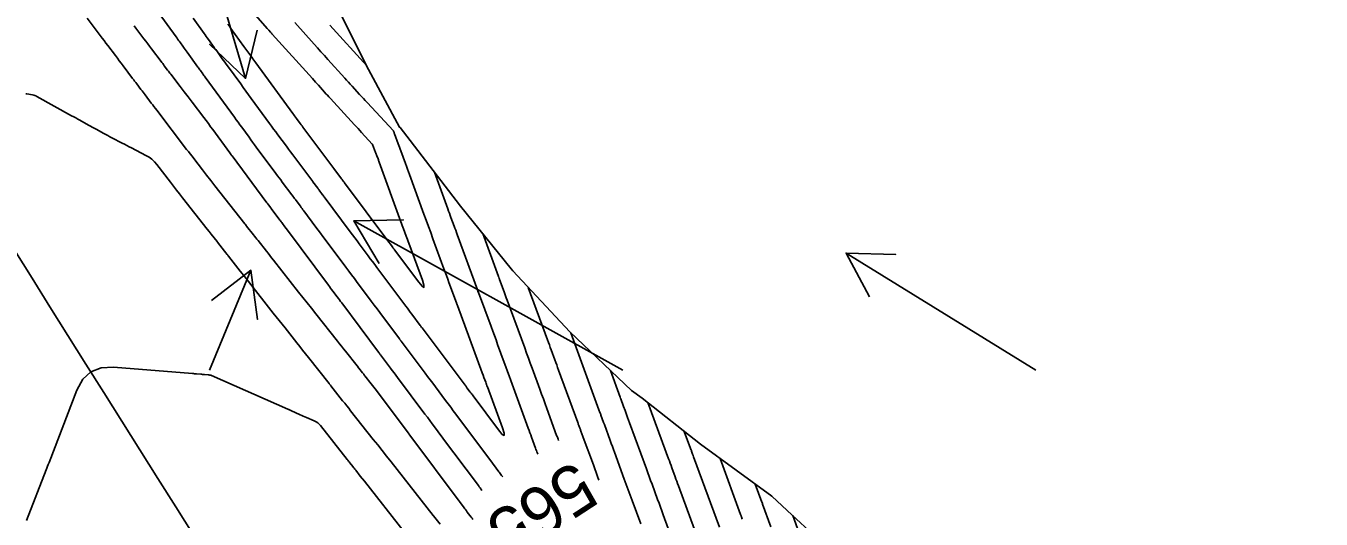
# Model space of a CAD drawing. Extents: x 954385 to 988206, y 1868364 to 1924553.
# Drawn here: x 957284.9 to 957441.7, y 1920650.9 to 1920710.5 of the extents above; entities that cross this region are included whole.
import ezdxf

# ---------------------------------------------------------------- set-up
doc = ezdxf.new("R2010")
doc.units = 0
for name, color, linetype in [('24', 7, 'Continuous'), ('26', 7, 'Continuous'), ('5', 7, 'Continuous'), ('6', 7, 'Continuous'), ('7', 7, 'Continuous'), ('Default', 7, 'Continuous')]:
    doc.layers.add(name, color=color, linetype=linetype)

msp = doc.modelspace()

# ---------------------------------------------------------------- linework, layer by layer
at = {"layer": '24'}
msp.add_lwpolyline([(957321.88, 1920714.2), (957326.37, 1920705.27), (957330.11, 1920698.3), (957330.2, 1920698.26), (957331.42, 1920696.68), (957337.51, 1920688.75), (957343.63, 1920681.18), (957343.82, 1920680.95), (957350.73, 1920673.54), (957358.19, 1920666.47), (957359.5, 1920665.55), (957366.53, 1920659.98), (957375.17, 1920653.68), (957377.65, 1920651.39), (957382.74, 1920646.71)], dxfattribs=at)
at = {"layer": '26'}
for points in [[(957307.13, 1920718.93), (957311.5, 1920704.2), (957307.14, 1920708.33), (957311.5, 1920704.2), (957312.9, 1920710.03)], [(957357.13, 1920668.93), (957324.58, 1920686.97), (957330.58, 1920687.08), (957324.58, 1920686.97), (957327.67, 1920681.83)], [(957407.13, 1920668.93), (957384.17, 1920683.08), (957390.17, 1920682.91), (957384.17, 1920683.08), (957387.02, 1920677.8)], [(957307.13, 1920668.93), (957312.14, 1920681.01), (957312.92, 1920675.06), (957312.14, 1920681.01), (957307.38, 1920677.36)]]:
    msp.add_lwpolyline(points, dxfattribs=at)
at = {"layer": '6'}
for points in [[(957300.93, 1920712.2), (957303.09, 1920709.21), (957303.2, 1920709.06), (957303.31, 1920708.9), (957303.42, 1920708.75), (957303.53, 1920708.6), (957303.97, 1920707.99), (957304.08, 1920707.84), (957304.19, 1920707.69), (957304.3, 1920707.53), (957304.41, 1920707.38), (957305.73, 1920705.56), (957305.8, 1920705.46), (957305.87, 1920705.36), (957305.94, 1920705.25), (957306.02, 1920705.15), (957306.31, 1920704.75), (957306.38, 1920704.65), (957306.45, 1920704.55), (957306.53, 1920704.45), (957306.6, 1920704.35), (957310.14, 1920699.5), (957310.36, 1920699.19), (957310.58, 1920698.89), (957310.8, 1920698.59), (957311.02, 1920698.29), (957311.91, 1920697.08), (957312.13, 1920696.78), (957312.35, 1920696.48), (957312.57, 1920696.18), (957312.79, 1920695.88), (957315.17, 1920692.69), (957315.36, 1920692.43), (957315.56, 1920692.18), (957315.75, 1920691.92), (957315.94, 1920691.66), (957317.08, 1920690.14), (957317.09, 1920690.12), (957317.12, 1920690.08), (957317.13, 1920690.07), (957317.42, 1920689.68), (957317.47, 1920689.62), (957317.52, 1920689.55), (957317.57, 1920689.48), (957317.62, 1920689.42), (957318.13, 1920688.73), (957318.23, 1920688.6), (957318.33, 1920688.46), (957318.43, 1920688.32), (957318.54, 1920688.19), (957320, 1920686.22), (957320.28, 1920685.85), (957320.56, 1920685.48), (957320.84, 1920685.1), (957321.11, 1920684.73), (957323.63, 1920681.36), (957323.98, 1920680.9), (957324.32, 1920680.44), (957324.66, 1920679.99), (957325, 1920679.53), (957326.37, 1920677.7), (957326.71, 1920677.25), (957327.05, 1920676.79), (957327.4, 1920676.33), (957327.74, 1920675.88), (957330.11, 1920672.7), (957330.14, 1920672.67), (957330.16, 1920672.64), (957330.21, 1920672.58), (957330.23, 1920672.55), (957330.25, 1920672.52), (957330.32, 1920672.44), (957330.34, 1920672.41), (957333.22, 1920668.57), (957333.53, 1920668.16), (957333.84, 1920667.75), (957334.15, 1920667.33), (957334.46, 1920666.92), (957335.7, 1920665.26), (957336.01, 1920664.85), (957336.32, 1920664.44), (957336.63, 1920664.02), (957336.94, 1920663.61), (957340.4, 1920658.98), (957341.04, 1920658.13), (957342.14, 1920656.65), (957342.22, 1920656.54), (957342.31, 1920656.43), (957342.39, 1920656.32), (957342.48, 1920656.2), (957342.61, 1920656.03)], [(957326.15, 1920705.7), (957321.7, 1920710.64)], [(957346.85, 1920658.78), (957346.81, 1920658.9), (957346.75, 1920659.05), (957346.69, 1920659.2), (957346.64, 1920659.35), (957346.58, 1920659.51), (957346.1, 1920660.82), (957346, 1920661.09), (957345.91, 1920661.36), (957345.81, 1920661.63), (957345.71, 1920661.9), (957343.59, 1920667.69), (957343.39, 1920668.23), (957343.19, 1920668.78), (957342.99, 1920669.32), (957342.79, 1920669.86), (957341.99, 1920672.02), (957341.8, 1920672.57), (957341.6, 1920673.11), (957341.4, 1920673.65), (957341.2, 1920674.19), (957339.69, 1920678.3), (957339.66, 1920678.35), (957339.62, 1920678.47), (957339.6, 1920678.52), (957339.57, 1920678.6), (957339.56, 1920678.65), (957337.11, 1920685.31), (957337.02, 1920685.57), (957336.92, 1920685.83), (957336.83, 1920686.09), (957336.73, 1920686.35), (957336.35, 1920687.38), (957336.26, 1920687.64), (957336.16, 1920687.9), (957336.07, 1920688.15), (957335.97, 1920688.41), (957334.36, 1920692.85)], [(957366.27, 1920648.44), (957363.88, 1920654.94), (957363.78, 1920655.22), (957363.68, 1920655.49), (957363.58, 1920655.76), (957363.48, 1920656.03), (957363.08, 1920657.12), (957362.98, 1920657.39), (957362.88, 1920657.67), (957362.78, 1920657.94), (957362.68, 1920658.21), (957360.18, 1920665.02)]]:
    msp.add_lwpolyline(points, dxfattribs=at)
at = {"layer": '7'}
for points in [[(957309.36, 1920710.74), (957309.54, 1920710.5), (957309.63, 1920710.37), (957309.72, 1920710.25), (957311.3, 1920708.06), (957311.42, 1920707.9), (957311.54, 1920707.73), (957311.66, 1920707.57), (957311.78, 1920707.4), (957312.26, 1920706.75), (957312.38, 1920706.58), (957312.5, 1920706.42), (957312.62, 1920706.25), (957312.74, 1920706.09), (957317.21, 1920699.97), (957317.32, 1920699.81), (957317.43, 1920699.66), (957317.54, 1920699.51), (957317.65, 1920699.36), (957318.11, 1920698.76), (957318.22, 1920698.6), (957318.33, 1920698.45), (957318.44, 1920698.3), (957318.56, 1920698.15), (957322.16, 1920693.32), (957322.18, 1920693.3), (957323.12, 1920692.05), (957323.18, 1920691.97), (957323.24, 1920691.89), (957323.36, 1920691.73), (957323.42, 1920691.65), (957323.47, 1920691.57), (957328.72, 1920684.54), (957328.86, 1920684.36), (957328.99, 1920684.18), (957329.26, 1920683.82), (957329.33, 1920683.73), (957329.39, 1920683.64), (957329.46, 1920683.55), (957329.53, 1920683.46), (957332.45, 1920679.55), (957332.86, 1920679.06), (957333.07, 1920678.93), (957333.08, 1920679.18), (957332.89, 1920679.79), (957331.24, 1920684.27), (957331.17, 1920684.48), (957331.09, 1920684.7), (957331.01, 1920684.92), (957330.93, 1920685.13), (957330.61, 1920686), (957330.53, 1920686.22), (957330.45, 1920686.43), (957330.37, 1920686.65), (957330.3, 1920686.87), (957327.66, 1920694.08), (957327.63, 1920694.18), (957327.59, 1920694.27), (957327.56, 1920694.37), (957327.52, 1920694.47), (957327.37, 1920694.85), (957327.34, 1920694.95), (957327.3, 1920695.04), (957327.26, 1920695.14), (957327.23, 1920695.24), (957326.87, 1920696.2), (957326.87, 1920696.21), (957326.87, 1920696.21), (957326.87, 1920696.22), (957326.86, 1920696.22), (957326.84, 1920696.24), (957326.83, 1920696.26), (957325.53, 1920697.66), (957325.32, 1920697.9), (957325.1, 1920698.13), (957324.88, 1920698.37), (957324.67, 1920698.6), (957321.77, 1920701.75), (957321.58, 1920701.95), (957321.4, 1920702.15), (957321.22, 1920702.35), (957321.04, 1920702.55), (957320.31, 1920703.36), (957319.94, 1920703.76), (957319.58, 1920704.17), (957314.73, 1920709.54), (957314.68, 1920709.6), (957314.62, 1920709.66), (957314.57, 1920709.72), (957314.52, 1920709.78), (957314.31, 1920710.02), (957314.2, 1920710.14), (957314.09, 1920710.25), (957312.15, 1920712.43)], [(957339.01, 1920650.86), (957338.9, 1920651.01), (957338.79, 1920651.15), (957338.33, 1920651.77), (957338.23, 1920651.9), (957338.13, 1920652.03), (957338.04, 1920652.16), (957337.94, 1920652.28), (957337.38, 1920653.03), (957337.25, 1920653.2), (957337.21, 1920653.26), (957331.62, 1920660.74), (957331.34, 1920661.11), (957331.29, 1920661.17), (957331.25, 1920661.23), (957331.2, 1920661.3), (957331.15, 1920661.36), (957327.32, 1920666.47), (957327.17, 1920666.67), (957327.02, 1920666.86), (957326.87, 1920667.06), (957326.71, 1920667.25), (957325.94, 1920668.23), (957325.86, 1920668.32), (957325.79, 1920668.42), (957325.71, 1920668.52), (957325.63, 1920668.61), (957325.21, 1920669.15), (957325.15, 1920669.22), (957325.02, 1920669.39), (957324.98, 1920669.44), (957323.57, 1920671.22), (957323.33, 1920671.52), (957323.09, 1920671.82), (957322.86, 1920672.12), (957322.62, 1920672.42), (957319.98, 1920675.75), (957319.46, 1920676.41), (957318.94, 1920677.06), (957318.42, 1920677.72), (957317.91, 1920678.37), (957314.86, 1920682.24), (957314.65, 1920682.51), (957314.43, 1920682.78), (957314.22, 1920683.05), (957314.01, 1920683.32), (957313.02, 1920684.58), (957312.87, 1920684.76), (957312.73, 1920684.94), (957312.59, 1920685.12), (957312.45, 1920685.3), (957311.62, 1920686.35), (957311.57, 1920686.42), (957311.49, 1920686.52), (957311.48, 1920686.52), (957311.45, 1920686.57), (957311.43, 1920686.58), (957311.42, 1920686.6), (957307.78, 1920691.21), (957307.52, 1920691.53), (957307.27, 1920691.85), (957306.76, 1920692.5), (957306.64, 1920692.66), (957306.51, 1920692.82), (957306.39, 1920692.98), (957306.26, 1920693.14), (957305.22, 1920694.5), (957305.01, 1920694.78), (957304.79, 1920695.06), (957304.58, 1920695.34), (957304.36, 1920695.62), (957300.75, 1920700.34), (957300.58, 1920700.56), (957300.41, 1920700.78), (957300.25, 1920700.99), (957300.08, 1920701.21), (957299.34, 1920702.2), (957299.21, 1920702.36), (957299.08, 1920702.53), (957298.96, 1920702.7), (957298.83, 1920702.86), (957298.33, 1920703.53), (957298.2, 1920703.7), (957298.07, 1920703.87), (957297.95, 1920704.03), (957297.82, 1920704.2), (957296.66, 1920705.73), (957296.44, 1920706.04), (957296.21, 1920706.34), (957295.98, 1920706.64), (957295.75, 1920706.95), (957294.83, 1920708.16), (957294.6, 1920708.46), (957294.37, 1920708.77), (957294.14, 1920709.07), (957293.91, 1920709.37), (957292.31, 1920711.48)], [(957298, 1920710.57), (957298.23, 1920710.26), (957299.19, 1920708.99), (957299.42, 1920708.69), (957299.65, 1920708.39), (957299.88, 1920708.09), (957300.1, 1920707.79), (957301.27, 1920706.24), (957301.37, 1920706.12), (957301.47, 1920705.99), (957301.56, 1920705.86), (957301.66, 1920705.73), (957302.05, 1920705.21), (957302.15, 1920705.08), (957302.25, 1920704.96), (957302.34, 1920704.83), (957302.44, 1920704.7), (957303.56, 1920703.21), (957303.68, 1920703.05), (957303.8, 1920702.9), (957303.93, 1920702.74), (957304.05, 1920702.58), (957304.53, 1920701.95), (957304.65, 1920701.79), (957304.77, 1920701.63), (957304.89, 1920701.47), (957305.02, 1920701.31), (957306.44, 1920699.46), (957306.72, 1920699.1), (957306.99, 1920698.73), (957307.26, 1920698.36), (957307.53, 1920698), (957309.58, 1920695.19), (957309.67, 1920695.07), (957309.76, 1920694.94), (957309.78, 1920694.91), (957309.81, 1920694.88), (957309.83, 1920694.85), (957309.85, 1920694.82), (957314.07, 1920689.16), (957314.17, 1920689.04), (957314.26, 1920688.91), (957314.53, 1920688.55), (957314.55, 1920688.53), (957314.58, 1920688.48), (957314.6, 1920688.46), (957314.69, 1920688.34), (957314.71, 1920688.31), (957315.64, 1920687.07), (957315.72, 1920686.97), (957315.79, 1920686.86), (957315.87, 1920686.76), (957315.95, 1920686.66), (957316.25, 1920686.24), (957316.41, 1920686.04), (957316.56, 1920685.83), (957321.51, 1920679.21), (957321.64, 1920679.03), (957321.78, 1920678.85), (957321.91, 1920678.67), (957322.05, 1920678.49), (957322.59, 1920677.77), (957322.72, 1920677.59), (957322.86, 1920677.41), (957322.99, 1920677.23), (957323.13, 1920677.05), (957327.59, 1920671.09), (957327.61, 1920671.06), (957327.64, 1920671.02), (957327.65, 1920671), (957327.76, 1920670.86), (957327.81, 1920670.79), (957329.04, 1920669.15), (957329.25, 1920668.87), (957329.46, 1920668.59), (957329.68, 1920668.31), (957329.89, 1920668.03), (957333.2, 1920663.61), (957333.49, 1920663.22), (957333.78, 1920662.83), (957334.08, 1920662.45), (957334.37, 1920662.06), (957335.82, 1920660.11), (957336.7, 1920658.94), (957339.67, 1920654.96), (957339.72, 1920654.89), (957339.77, 1920654.82), (957339.82, 1920654.76), (957339.87, 1920654.69), (957340.1, 1920654.39)], [(957317.45, 1920710.94), (957319.79, 1920708.34), (957320.21, 1920707.88), (957320.62, 1920707.42), (957321.04, 1920706.96), (957321.45, 1920706.5), (957323.49, 1920704.24), (957323.72, 1920703.99), (957323.94, 1920703.74), (957324.17, 1920703.5), (957324.39, 1920703.25), (957325.3, 1920702.27), (957325.52, 1920702.02), (957325.75, 1920701.78), (957325.98, 1920701.53), (957326.2, 1920701.29), (957329.38, 1920697.85), (957329.38, 1920697.84), (957329.39, 1920697.83), (957329.46, 1920697.64), (957329.47, 1920697.61), (957329.48, 1920697.57), (957329.49, 1920697.54), (957329.51, 1920697.51), (957329.97, 1920696.3), (957330.05, 1920696.08), (957330.13, 1920695.87), (957330.21, 1920695.65), (957330.29, 1920695.44), (957330.85, 1920693.9), (957330.97, 1920693.57), (957331.09, 1920693.24), (957331.21, 1920692.91), (957331.33, 1920692.58), (957333.08, 1920687.79), (957333.35, 1920687.04), (957333.63, 1920686.3), (957333.9, 1920685.55), (957334.17, 1920684.81), (957335.5, 1920681.18), (957335.66, 1920680.76), (957335.81, 1920680.35), (957335.96, 1920679.93), (957336.11, 1920679.52), (957337.01, 1920677.07), (957337.03, 1920677.02), (957337.05, 1920676.96), (957337.1, 1920676.81), (957337.11, 1920676.79), (957337.14, 1920676.72), (957340.13, 1920668.59), (957340.24, 1920668.31), (957340.34, 1920668.02), (957340.55, 1920667.46), (957340.6, 1920667.31), (957340.65, 1920667.17), (957340.7, 1920667.03), (957340.76, 1920666.89), (957342.57, 1920661.94), (957342.77, 1920661.29), (957342.77, 1920661.03), (957342.54, 1920661.16), (957342.11, 1920661.69), (957339.02, 1920665.82), (957338.94, 1920665.93), (957338.86, 1920666.04), (957338.78, 1920666.15), (957338.69, 1920666.26), (957338.29, 1920666.8), (957338.13, 1920667.01), (957338.05, 1920667.12), (957332.86, 1920674.02), (957332.82, 1920674.08), (957332.8, 1920674.1), (957332.71, 1920674.23), (957332.69, 1920674.25), (957332.68, 1920674.27), (957332.66, 1920674.3), (957332.64, 1920674.32), (957331.61, 1920675.7), (957331.43, 1920675.94), (957331.25, 1920676.17), (957331.07, 1920676.41), (957330.9, 1920676.65), (957327.39, 1920681.32), (957327.12, 1920681.68), (957326.86, 1920682.04), (957326.59, 1920682.4), (957326.32, 1920682.76), (957325.25, 1920684.2), (957324.98, 1920684.56), (957324.71, 1920684.92), (957324.44, 1920685.28), (957324.17, 1920685.64), (957321.01, 1920689.88), (957320.94, 1920689.97), (957320.87, 1920690.06), (957320.81, 1920690.14), (957320.74, 1920690.23), (957320.48, 1920690.58), (957320.41, 1920690.67), (957320.35, 1920690.76), (957320.28, 1920690.85), (957320.22, 1920690.93), (957319.65, 1920691.69), (957319.64, 1920691.7), (957319.62, 1920691.73), (957317.46, 1920694.63), (957317.2, 1920694.97), (957316.94, 1920695.32), (957316.69, 1920695.66), (957316.43, 1920696), (957315.4, 1920697.38), (957315.15, 1920697.72), (957314.89, 1920698.07), (957314.64, 1920698.42), (957314.38, 1920698.76), (957312.18, 1920701.78), (957311.86, 1920702.22), (957311.54, 1920702.65), (957311.22, 1920703.09), (957310.91, 1920703.53), (957309.31, 1920705.71), (957309.15, 1920705.93), (957309, 1920706.14), (957308.84, 1920706.36), (957308.68, 1920706.57), (957308.01, 1920707.51), (957307.88, 1920707.69), (957307.75, 1920707.86), (957307.62, 1920708.04), (957307.5, 1920708.22), (957306.99, 1920708.92), (957306.86, 1920709.1), (957306.73, 1920709.28), (957306.6, 1920709.45), (957306.48, 1920709.63), (957305.14, 1920711.48)], [(957335.03, 1920650.32), (957334.4, 1920651.12), (957334.24, 1920651.32), (957334.2, 1920651.37), (957329.1, 1920657.84), (957328.56, 1920658.52), (957328.02, 1920659.2), (957327.49, 1920659.88), (957326.95, 1920660.55), (957324.21, 1920664.01), (957323.97, 1920664.31), (957323.73, 1920664.62), (957323.49, 1920664.92), (957323.24, 1920665.23), (957321.82, 1920667.03), (957321.76, 1920667.1), (957321.61, 1920667.28), (957321.59, 1920667.32), (957319.11, 1920670.45), (957318.75, 1920670.9), (957318.4, 1920671.34), (957318.04, 1920671.79), (957317.69, 1920672.24), (957316.27, 1920674.03), (957315.91, 1920674.48), (957315.56, 1920674.93), (957315.2, 1920675.38), (957314.85, 1920675.83), (957311.84, 1920679.64), (957311.59, 1920679.96), (957311.34, 1920680.28), (957311.09, 1920680.59), (957310.84, 1920680.91), (957309.42, 1920682.71), (957309.38, 1920682.76), (957309.34, 1920682.81), (957309.3, 1920682.86), (957309.26, 1920682.91), (957309.07, 1920683.16), (957308.99, 1920683.26), (957308.95, 1920683.31), (957308.11, 1920684.38), (957308.09, 1920684.4), (957308.06, 1920684.44), (957308.05, 1920684.44), (957308.04, 1920684.46), (957308.04, 1920684.46), (957307.32, 1920685.37), (957307.08, 1920685.68), (957306.84, 1920685.98), (957303.86, 1920689.76), (957303.49, 1920690.23), (957303.13, 1920690.7), (957302.76, 1920691.17), (957302.39, 1920691.64), (957300.74, 1920693.8), (957300.46, 1920694.12), (957300.15, 1920694.42), (957299.81, 1920694.67), (957299.44, 1920694.89), (957297.69, 1920695.79), (957297.4, 1920695.94), (957297.11, 1920696.09), (957296.82, 1920696.23), (957296.54, 1920696.38), (957295.29, 1920697.03), (957295.05, 1920697.15), (957294.82, 1920697.28), (957294.58, 1920697.4), (957294.35, 1920697.53), (957293.41, 1920698.05), (957293.18, 1920698.17), (957292.94, 1920698.3), (957292.71, 1920698.43), (957292.48, 1920698.56), (957291.44, 1920699.13), (957291.19, 1920699.27), (957290.94, 1920699.41), (957290.69, 1920699.55), (957290.44, 1920699.69), (957286.23, 1920702.02), (957286.11, 1920702.08), (957285.98, 1920702.13), (957285.85, 1920702.17), (957285.71, 1920702.2), (957285.04, 1920702.32), (957284.96, 1920702.33), (957284.89, 1920702.35)], [(957349.37, 1920660.43), (957349.32, 1920660.57), (957349.27, 1920660.69), (957349.23, 1920660.81), (957349.19, 1920660.92), (957349.14, 1920661.04), (957347.95, 1920664.29), (957347.74, 1920664.87), (957347.53, 1920665.45), (957347.32, 1920666.04), (957347.1, 1920666.62), (957346.18, 1920669.15), (957345.95, 1920669.76), (957345.73, 1920670.38), (957345.5, 1920670.99), (957345.27, 1920671.61), (957343.14, 1920677.4), (957343.05, 1920677.65), (957342.96, 1920677.91), (957342.86, 1920678.16), (957342.77, 1920678.41), (957342.23, 1920679.88), (957342.21, 1920679.93), (957342.19, 1920679.99), (957342.13, 1920680.16), (957342.1, 1920680.22), (957342.1, 1920680.23), (957340.19, 1920685.43)], [(957345.71, 1920678.92), (957348.04, 1920672.59), (957348.15, 1920672.28), (957348.26, 1920671.98), (957348.37, 1920671.68), (957348.49, 1920671.37), (957348.93, 1920670.16), (957349.04, 1920669.85), (957349.15, 1920669.55), (957349.26, 1920669.25), (957349.38, 1920668.94), (957351.7, 1920662.58), (957351.73, 1920662.5), (957351.76, 1920662.41), (957351.8, 1920662.33), (957351.83, 1920662.24), (957351.95, 1920661.9), (957351.98, 1920661.82), (957352.01, 1920661.73), (957352.04, 1920661.65), (957352.08, 1920661.56), (957352.32, 1920660.89), (957352.36, 1920660.8), (957353.58, 1920657.47), (957353.75, 1920657.01), (957353.92, 1920656.55), (957354.09, 1920656.08), (957354.26, 1920655.62)], [(957350.86, 1920673.42), (957354.26, 1920664.12), (957354.3, 1920664.01), (957354.34, 1920663.91), (957354.43, 1920663.66), (957354.47, 1920663.55), (957354.49, 1920663.5), (957354.82, 1920662.59), (957354.92, 1920662.34), (957355.62, 1920660.43), (957355.75, 1920660.07), (957355.88, 1920659.71), (957356.01, 1920659.35), (957356.14, 1920658.99), (957357.33, 1920655.75), (957357.57, 1920655.1), (957357.81, 1920654.45), (957358.05, 1920653.8), (957358.29, 1920653.15), (957359.33, 1920650.34)], [(957330.7, 1920649.38), (957325.88, 1920655.5), (957325.38, 1920656.12), (957324.82, 1920656.85), (957324.73, 1920656.95), (957324.64, 1920657.06), (957324.56, 1920657.17), (957324.47, 1920657.28), (957324.13, 1920657.71), (957324.04, 1920657.82), (957323.96, 1920657.93), (957323.87, 1920658.04), (957323.79, 1920658.14), (957320.55, 1920662.22), (957320.39, 1920662.4), (957320.22, 1920662.55), (957320.02, 1920662.68), (957319.81, 1920662.79), (957318.85, 1920663.21), (957318.67, 1920663.29), (957318.48, 1920663.38), (957318.29, 1920663.46), (957318.11, 1920663.54), (957316.99, 1920664.03), (957316.89, 1920664.07), (957316.72, 1920664.15), (957316.66, 1920664.18), (957316.6, 1920664.2), (957307.38, 1920668.26), (957307.28, 1920668.3), (957307.17, 1920668.33), (957307.06, 1920668.35), (957306.95, 1920668.36), (957306.51, 1920668.4), (957306.4, 1920668.41), (957306.29, 1920668.41), (957306.17, 1920668.42), (957306.06, 1920668.43), (957305.56, 1920668.47), (957305.44, 1920668.48), (957305.31, 1920668.49), (957305.19, 1920668.5), (957305.07, 1920668.51), (957295.51, 1920669.29), (957294.01, 1920669.21), (957292.77, 1920668.72), (957291.79, 1920667.82), (957291.07, 1920666.49), (957287.71, 1920657.74), (957287.62, 1920657.52), (957287.54, 1920657.31), (957287.45, 1920657.09), (957287.37, 1920656.87), (957284.99, 1920650.74)], [(957363.7, 1920646.93), (957362.04, 1920651.45), (957361.87, 1920651.91), (957361.7, 1920652.37), (957361.53, 1920652.83), (957361.36, 1920653.29), (957360.68, 1920655.14), (957360.51, 1920655.6), (957360.35, 1920656.06), (957360.18, 1920656.52), (957360.01, 1920656.98), (957357.96, 1920662.54), (957357.84, 1920662.87), (957357.72, 1920663.2), (957357.42, 1920664.03), (957357.24, 1920664.52), (957356.9, 1920665.44), (957356.87, 1920665.51), (957356.83, 1920665.64), (957356.82, 1920665.65), (957355.64, 1920668.89)], [(957368.84, 1920649.95), (957365.72, 1920658.44), (957365.66, 1920658.61), (957365.6, 1920658.77), (957365.47, 1920659.11), (957365.44, 1920659.19), (957365.41, 1920659.27), (957365.38, 1920659.35), (957365.35, 1920659.44), (957364.59, 1920661.51)], [(957371.61, 1920650.9), (957371.51, 1920651.18), (957371.49, 1920651.25), (957371.46, 1920651.32), (957371.43, 1920651.39), (957371.41, 1920651.46), (957368.92, 1920658.24)], [(957375.08, 1920649.99), (957374.07, 1920652.71), (957374.04, 1920652.8), (957374, 1920652.91), (957373.98, 1920652.98), (957373.18, 1920655.13)], [(957377.71, 1920651.34), (957379.92, 1920645.27)]]:
    msp.add_lwpolyline(points, dxfattribs=at)
at = {"layer": 'Default'}
msp.add_arc((966995.78, 1926764.93), 11459.16, 211.460692, 214.075074, dxfattribs=at)

# ---------------------------------------------------------------- texts
at = {"layer": '5'}
msp.add_text('565', height=6, rotation=213.0663, dxfattribs=at).set_placement((957351.35, 1920658.13))

doc.saveas('drawing.dxf')
